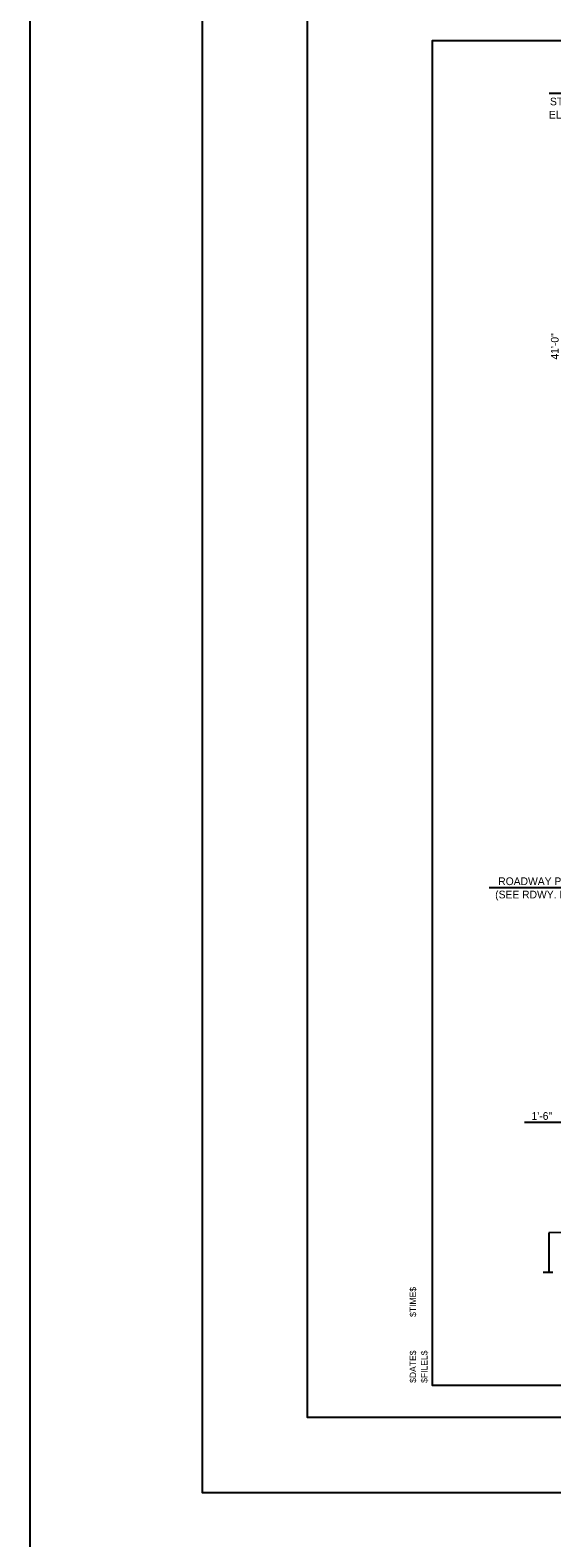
# Model space of a CAD drawing. Extents: x 570 to 2152770, y 726 to 141756.
# Drawn here: x 2151191 to 2151256.2, y 141472 to 141660.3 of the extents above; entities that cross this region are included whole.
import ezdxf

# ---------------------------------------------------------------- set-up
doc = ezdxf.new("R2010")
doc.units = 0
for name, color, linetype in [('2', 7, 'Continuous'), ('8', 7, 'Continuous'), ('PR_Dimensions', 7, 'Continuous'), ('SHT_Plot_Shape_Full', 7, 'Continuous'), ('SHT_Plot_Shape_Half', 7, 'Continuous'), ('SHT_Plot_Stamp', 7, 'Continuous'), ('SHT_Sheet_Border', 7, 'Continuous'), ('T', 7, 'Continuous')]:
    doc.layers.add(name, color=color, linetype=linetype)

# ---------------------------------------------------------------- blocks, each defined once
blk = doc.blocks.new('Stamp_Plot_Stamp')
at = {"layer": 'SHT_Plot_Stamp'}
for s, p in [('$TIME$', (1.695, 1.572)), ('$DATE$', (1.695, 0.542)), ('$FILEL$', (1.873, 0.542))]:
    blk.add_text(s, height=0.1, rotation=90, dxfattribs=at).set_placement(p)

msp = doc.modelspace()

# ---------------------------------------------------------------- linework, layer by layer
at = {"layer": '2'}
for p, q in [((2151257.53, 141510.17), (2151255.78, 141510.11)), ((2151255.78, 141510.11), (2151255.78, 141505.2))]:
    msp.add_line(p, q, dxfattribs=at)
at = {"layer": '8'}
msp.add_lwpolyline([(2151191.03, 141756.43), (2151532.18, 141756.43), (2151532.18, 141194.31), (2151191.03, 141194.31)], close=True, dxfattribs=at)
at = {"layer": 'PR_Dimensions'}
for p, q in [((2151268.4, 141652.4), (2151255.83, 141652.42)), ((2151262.32, 141553.22), (2151248.33, 141553.22)), ((2151257.66, 141523.89), (2151252.74, 141523.89)), ((2151255.06, 141505.2), (2151256.26, 141505.2))]:
    msp.add_line(p, q, dxfattribs=at)
at = {"layer": 'SHT_Plot_Shape_Full'}
msp.add_lwpolyline([(2151212.55, 141669.65), (2151500.55, 141669.65), (2151500.55, 141477.65), (2151212.55, 141477.65)], close=True, dxfattribs=at)
at = {"layer": 'SHT_Plot_Shape_Half'}
msp.add_lwpolyline([(2151225.65, 141663.05), (2151497.65, 141663.05), (2151497.65, 141487.05), (2151225.65, 141487.05)], close=True, dxfattribs=at)
at = {"layer": 'SHT_Sheet_Border'}
msp.add_lwpolyline([(2151493.25, 141491.05), (2151241.25, 141491.05), (2151241.25, 141659.05), (2151493.25, 141659.05)], close=True, dxfattribs=at)

# ---------------------------------------------------------------- block references
at = {"layer": 'SHT_Plot_Stamp', "xscale": 8.000000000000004, "yscale": 8.000000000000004}
msp.add_blockref('Stamp_Plot_Stamp', (2151225.65, 141487.05), dxfattribs=at)

# ---------------------------------------------------------------- texts
at = {"layer": 'T'}
for s, height, rotation, p in [('STA. 72+84.51', 0.9635, 0.0754, (2151255.92, 141650.95)), ('ELEV. 1301.59', 0.9635, 0.0754, (2151255.79, 141649.3)), ('41\'-0"', 0.964, 90, (2151257, 141619.2))]:
    msp.add_text(s, height=height, rotation=rotation, dxfattribs=at).set_placement(p)
for s, height, p in [('ROADWAY PAVING', 0.9635, (2151249.46, 141553.56)), ('(SEE RDWY. PLANS)', 0.9635, (2151249.08, 141551.9)), ('1\'-6"', 0.964, (2151253.62, 141524.24))]:
    msp.add_text(s, height=height, dxfattribs=at).set_placement(p)

doc.saveas('drawing.dxf')
